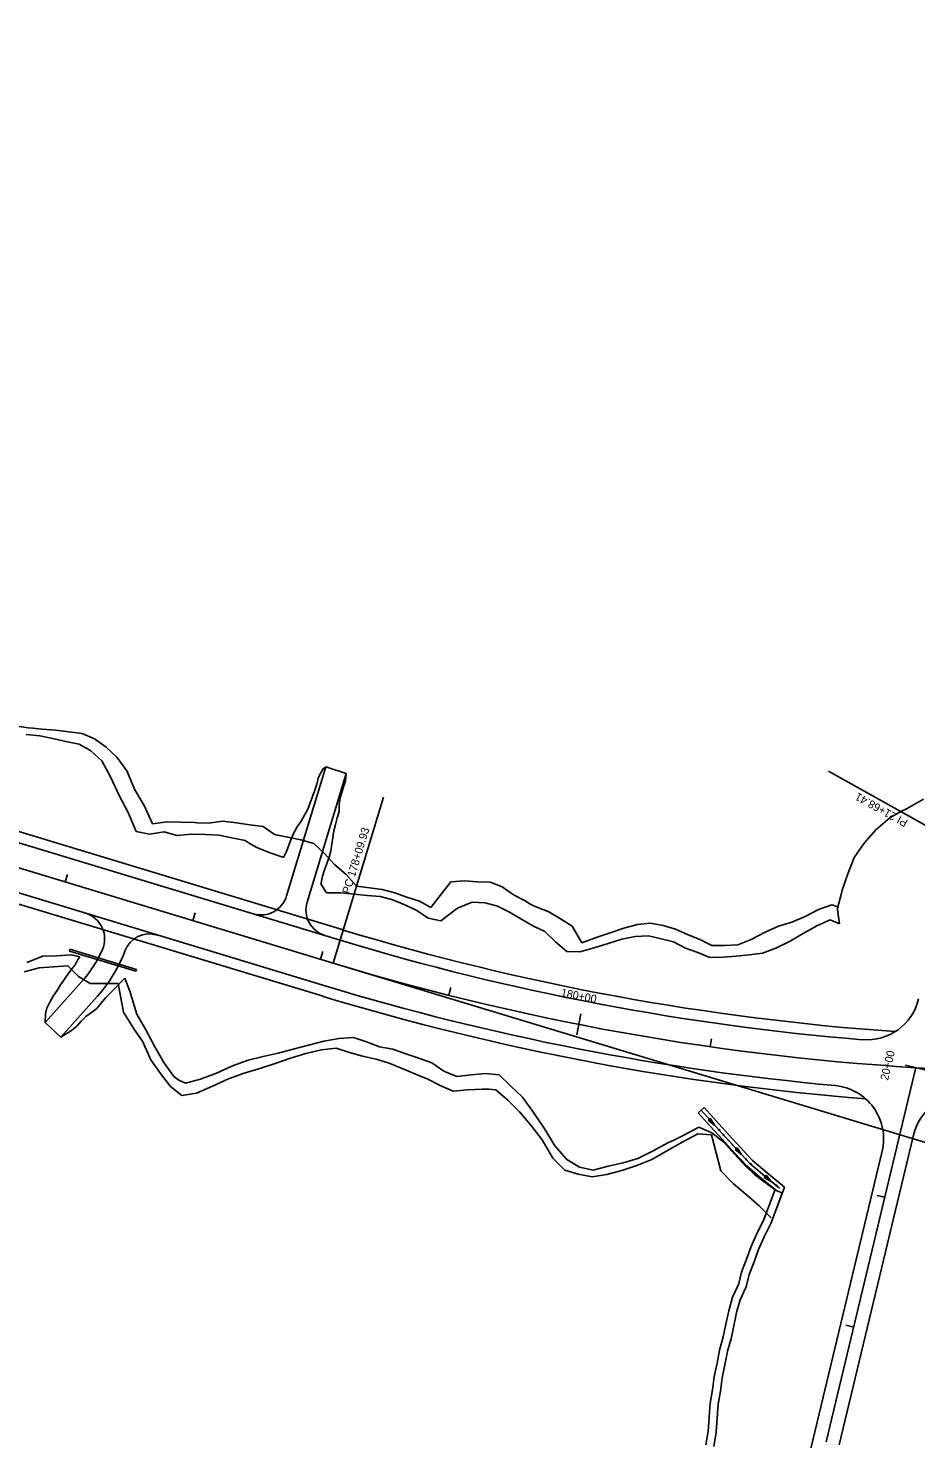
# Model space of a CAD drawing. Extents: x 979959 to 994833, y 1835619 to 1845316.
# Drawn here: x 983405 to 984070, y 1837450 to 1838507 of the extents above; entities that cross this region are included whole.
import ezdxf

# ---------------------------------------------------------------- set-up
doc = ezdxf.new("R2010")
doc.units = 0
for name, color, linetype in [('Future 5 Lane Construction Limits', 7, 'Continuous'), ('R_CONCRETE', 7, 'Continuous'), ('R_Drainage', 7, 'Continuous'), ('R_Horz Alg', 7, 'Continuous'), ('R_Horz Alg Annot', 7, 'Continuous'), ('R_Horz Alg Annot_Side Road', 7, 'Continuous'), ('R_Horz Alg Stationing', 7, 'Continuous'), ('R_Horz Alg Stationing_Side Road', 7, 'Continuous'), ('R_Proposed Const Limits', 7, 'Continuous'), ('R_Proposed Road', 7, 'Continuous'), ('R_Special Ditch', 7, 'Continuous')]:
    doc.layers.add(name, color=color, linetype=linetype)

msp = doc.modelspace()

# ---------------------------------------------------------------- linework, layer by layer
at = {"layer": 'Future 5 Lane Construction Limits'}
for points in [[(983394.6, 1837984.2), (983404.6, 1837982.7), (983408.1, 1837982.4), (983414.8, 1837981.8), (983425, 1837980.9), (983435.1, 1837979.8), (983445.1, 1837978.4), (983454.4, 1837974.4), (983463, 1837968.3), (983471.1, 1837960.8), (983478.5, 1837950.5), (983484.6, 1837936.2), (983491.5, 1837924.6), (983497.8, 1837910.8)], [(983497.8, 1837910.8), (983508.7, 1837912.4), (983519.1, 1837912.1), (983529.4, 1837911.7), (983531.3, 1837911.6), (983539.7, 1837911.3), (983550.6, 1837912.7), (983560.7, 1837911.5), (983570.7, 1837910.1), (983580.8, 1837908.7), (983589.4, 1837902.9), (983599.2, 1837900.7), (983609.1, 1837898.9), (983618.7, 1837896), (983626.9, 1837888.6), (983634.7, 1837880), (983643, 1837872.7), (983650.8, 1837864)], [(983650.8, 1837864), (983660.6, 1837862.9), (983670.2, 1837861.5), (983679.6, 1837859), (983688.7, 1837855.8), (983698, 1837852.9), (983706.7, 1837848.1)], [(983706.7, 1837848.1), (983721.7, 1837867.2), (983731.8, 1837868), (983741.4, 1837867.2), (983751.2, 1837867), (983760.2, 1837863.6), (983768.6, 1837857.5), (983777.3, 1837853), (983781.6, 1837850.3), (983786.1, 1837848.3), (983795.2, 1837844.9), (983803.8, 1837839.6), (983812.5, 1837834.2), (983819.8, 1837821.7)], [(983819.8, 1837821.7), (983830.5, 1837825.7), (983841, 1837829.1), (983851.4, 1837832.7), (983861.6, 1837835.3), (983871.5, 1837836.3), (983881, 1837834.6), (983890.2, 1837831.9), (983899.2, 1837827.8), (983908.3, 1837824.1), (983917.4, 1837819.6), (983927.1, 1837819.5), (983936.8, 1837820), (983947, 1837824.1), (983957.4, 1837829.6), (983967.5, 1837834), (983977.4, 1837837.1), (983987.4, 1837841.4), (983997.5, 1837846.6), (984007.3, 1837850), (984011.7, 1837848.7)], [(983401.6, 1837799.9), (983412.9, 1837802.8), (983423.6, 1837803.7), (983434.2, 1837804.3)], [(983434.2, 1837804.3), (983442.3, 1837796.3), (983451.1, 1837791), (983461.6, 1837791.2), (983472, 1837791.1)], [(983472, 1837791.1), (983476, 1837769.6), (983483, 1837758.3), (983484.4, 1837756.4), (983490.3, 1837747.9), (983496.5, 1837733.8), (983503.9, 1837723.6), (983511.4, 1837714), (983519.8, 1837707.2), (983530.8, 1837709), (983542.8, 1837714.1), (983554.9, 1837719.7), (983566.6, 1837723.8), (983578.2, 1837727.5), (983589.7, 1837731.1), (983601.4, 1837735.2), (983612.9, 1837738.7), (983624.5, 1837741.4), (983635.7, 1837742.7)], [(983635.7, 1837742.7), (983645.5, 1837739.5), (983655.4, 1837736.7), (983665.5, 1837734.3), (983675.4, 1837731.5), (983685, 1837727.4), (983694.6, 1837723.5), (983704.3, 1837719.5), (983713.7, 1837714.7), (983723.3, 1837710.4), (983734.2, 1837711.3), (983745, 1837712), (983750.2, 1837712), (983755.4, 1837711.5)], [(983755.4, 1837711.5), (983764.3, 1837703.6), (983773, 1837694.9), (983781.5, 1837684.9), (983790, 1837673.9), (983798, 1837660.3), (983807, 1837651.3), (983817.1, 1837648.3), (983827.5, 1837646.3), (983838.6, 1837648), (983849.8, 1837651), (983861.1, 1837654.6), (983872.4, 1837659.3), (983884.1, 1837666), (983895.6, 1837672.4), (983906.9, 1837678.4), (983917.2, 1837677.6)], [(983917.2, 1837677.6), (983924.1, 1837650.6), (983933.5, 1837641.2), (983943.1, 1837633), (983952.7, 1837624.8), (983961.9, 1837615.4)]]:
    msp.add_lwpolyline(points, dxfattribs=at)
at = {"layer": 'R_CONCRETE'}
msp.add_line((983907.2, 1837694.2), (983911.7, 1837698.2), dxfattribs=at)
for points in [[(983907.2, 1837694.2), (983916.2, 1837684.2), (983925.3, 1837674.1), (983934.4, 1837664.2), (983943.8, 1837654.2), (983953.5, 1837645.9), (983964.8, 1837636.6)], [(983911.7, 1837698.2), (983920.6, 1837688.2), (983929.7, 1837678.2), (983938.8, 1837668.3), (983948, 1837658.5), (983957.4, 1837650.5), (983971.9, 1837638.5)], [(983913, 1837445.2), (983914.6, 1837455.3), (983915.3, 1837466), (983916.2, 1837476.5), (983917.9, 1837486.5), (983919.1, 1837496.6), (983921.3, 1837506.6), (983923.2, 1837516.4), (983923.6, 1837518.1), (983926, 1837526.3), (983928, 1837535.8), (983930.1, 1837545.8), (983933, 1837556.1), (983937.4, 1837565.5), (983937.7, 1837566.3), (983939.7, 1837574.8), (983943.5, 1837584.5), (983946.9, 1837594.1), (983951.1, 1837603.7), (983955.8, 1837613), (983956.3, 1837614.1), (983964.8, 1837636.6)], [(983918.9, 1837444.1), (983920.6, 1837454.7), (983921.3, 1837465.5), (983922.2, 1837475.7), (983923.8, 1837485.6), (983925.1, 1837495.6), (983927.2, 1837505.4), (983929.1, 1837515.2), (983929.4, 1837516.6), (983931.8, 1837524.8), (983933.9, 1837534.6), (983935.9, 1837544.4), (983938.7, 1837554), (983943, 1837563.3), (983943.4, 1837564.7), (983945.4, 1837573), (983949.1, 1837582.4), (983952.5, 1837591.8), (983956.6, 1837601.2), (983961.1, 1837610.3), (983961.8, 1837611.7), (983971.9, 1837638.5)]]:
    msp.add_lwpolyline(points, dxfattribs=at)
at = {"layer": 'R_Drainage'}
for p, q in [((983435.9, 1837816.8), (983435.5, 1837815.3)), ((983485.3, 1837800.3), (983435.5, 1837815.3)), ((983485.7, 1837801.7), (983435.9, 1837816.8)), ((983485.7, 1837801.7), (983485.3, 1837800.3))]:
    msp.add_line(p, q, dxfattribs=at)
at = {"layer": 'R_Horz Alg'}
for p, q in [((981399.3, 1838482.3), (983633.3, 1837806.4)), ((984003.1, 1837447.5), (984070.4, 1837728.1))]:
    msp.add_line(p, q, dxfattribs=at)
msp.add_arc((984186.3, 1839634.4), 1909.9, 253.1679, 281.6644, dxfattribs=at)
at = {"layer": 'R_Horz Alg Annot'}
msp.add_lwpolyline([(983633.3, 1837806.4), (983671, 1837930.8)], dxfattribs=at)
at = {"layer": 'R_Horz Alg Annot_Side Road'}
msp.add_line((983633.3, 1837806.4), (984097.5, 1837666), dxfattribs=at)
msp.add_lwpolyline([(984109.7, 1837891.9), (984004.8, 1837950.2)], dxfattribs=at)
at = {"layer": 'R_Horz Alg Stationing'}
for points in [[(983434.1, 1837872.9), (983432.4, 1837867.2)], [(983529.8, 1837844), (983528.1, 1837838.2)], [(983625.5, 1837815), (983623.8, 1837809.3)], [(983721.6, 1837788.2), (983720.1, 1837782.4)], [(983819.2, 1837768.4), (983816.1, 1837752.7)], [(983917.1, 1837749.7), (983916.2, 1837743.8)]]:
    msp.add_lwpolyline(points, dxfattribs=at)
at = {"layer": 'R_Horz Alg Stationing_Side Road'}
for points in [[(984062.6, 1837730), (984078.2, 1837726.2)], [(984041.3, 1837632.3), (984047.1, 1837630.9)], [(984018, 1837535), (984023.8, 1837533.6)]]:
    msp.add_lwpolyline(points, dxfattribs=at)
at = {"layer": 'R_Proposed Const Limits'}
for p, q in [((983896.3, 1837677.5), (983907.6, 1837683.4)), ((983926.3, 1837672.2), (983934.3, 1837663.2)), ((983934.3, 1837663.2), (983943.4, 1837653.5))]:
    msp.add_line(p, q, dxfattribs=at)
for points in [[(983403.1, 1837977.8), (983413.2, 1837976.7), (983423.1, 1837974.7), (983432.9, 1837972.5), (983442.7, 1837970.4), (983448.1, 1837967.5), (983448.2, 1837967.5), (983451.6, 1837965.4), (983459.8, 1837958), (983466.5, 1837945.4), (983472.9, 1837932.1), (983479.5, 1837919.2), (983480.9, 1837916.4), (983485.6, 1837905.1)], [(983622.3, 1837945.7), (983625.5, 1837951.8), (983627.8, 1837953.6)], [(983624.1, 1837865.9), (983624.4, 1837866.3), (983624.4, 1837866.6), (983625.4, 1837871.5), (983626.8, 1837876.3), (983628.6, 1837881), (983630.3, 1837885.7), (983631.6, 1837890.5), (983632.4, 1837895.5), (983633, 1837900.5), (983633.8, 1837905.5), (983635, 1837910.4), (983636.4, 1837915.2), (983637.8, 1837920), (983637.8, 1837925.2), (983638.5, 1837930.2), (983640, 1837935), (983641.1, 1837938.6), (983642.7, 1837943), (983643.1, 1837948.5)], [(983596.1, 1837885.5), (983596.1, 1837885.6), (983598.4, 1837890.1), (983600, 1837894.8), (983601.9, 1837899.5), (983603.8, 1837904.1), (983606.4, 1837908.6), (983609.2, 1837912.9), (983611.8, 1837917.4), (983614.2, 1837921.9), (983616.1, 1837926.5), (983617.9, 1837931.2), (983619.6, 1837935.9), (983621.1, 1837940.5), (983622.3, 1837945.7)], [(984013.2, 1837835.9), (984011.7, 1837846.4), (984011.8, 1837848.6), (984014.3, 1837857.9), (984015.2, 1837861.1), (984019.5, 1837873.4), (984024.2, 1837885.5), (984031.6, 1837896.4), (984040.5, 1837906.4), (984050.9, 1837915.4), (984059.2, 1837920), (984063.8, 1837922.4), (984076.2, 1837929.3)], [(983485.6, 1837905.1), (983495.5, 1837903.1), (983506.5, 1837904.9), (983516.1, 1837902.1), (983526.8, 1837903), (983537.2, 1837902.9), (983547.5, 1837902.3), (983557.3, 1837900.2), (983567.2, 1837898.4), (983571.1, 1837895.7), (983576, 1837893.1), (983585.3, 1837889.2), (983594.8, 1837886), (983596.1, 1837885.5)], [(983624.1, 1837865.9), (983628.4, 1837859.1)], [(983628.4, 1837859.1), (983638.8, 1837859), (983649, 1837858), (983658.8, 1837857), (983668.7, 1837856.3), (983678.1, 1837853.7), (983687.2, 1837850.2), (983696, 1837845.8), (983704.5, 1837840)], [(983704.5, 1837840), (983714.1, 1837838), (983726.5, 1837847.5), (983737.6, 1837852), (983737.6, 1837852), (983747.4, 1837851.6), (983756.7, 1837849.1), (983765.5, 1837844.6), (983774.2, 1837839.5), (983783, 1837834.3), (983792, 1837830.2), (983800.2, 1837822.4), (983808.6, 1837815.1)], [(983808.6, 1837815.1), (983818.4, 1837814.8), (983829, 1837817.9), (983839.5, 1837821.2), (983849.9, 1837824.4), (983860, 1837826.4), (983869.9, 1837826.8), (983879.3, 1837824.7), (983888.6, 1837822.3), (983897.6, 1837817.6), (983906.9, 1837814.4), (983910, 1837813.1), (983916, 1837810.5), (983925.8, 1837810.9), (983935.7, 1837811.5), (983945.5, 1837812.7), (983955.4, 1837813.9), (983965.5, 1837817.7), (983975.7, 1837822.5), (983986, 1837828.5), (983996.2, 1837834.4), (984006.2, 1837838.9), (984013.2, 1837835.9)], [(983403.6, 1837806.8), (983415.6, 1837811.6), (983426.1, 1837811.9), (983436.7, 1837812.6), (983443.3, 1837811.1)], [(983443.3, 1837811.1), (983441.6, 1837808.7), (983439.8, 1837805.1), (983437.3, 1837802), (983434.6, 1837798.4), (983431.7, 1837794.3), (983428.8, 1837790.2), (983426.2, 1837785.8), (983423.4, 1837781.6), (983420.8, 1837777.2), (983418.5, 1837772.6), (983417.6, 1837768.5), (983417.2, 1837761.8)], [(983477.1, 1837795.2), (983474.9, 1837792.9), (983470.8, 1837788.7), (983466.7, 1837784.6), (983462.7, 1837780.5), (983459.3, 1837776.3), (983456.1, 1837772.4), (983452.1, 1837769.4), (983447.9, 1837766.4), (983444.4, 1837762.8), (983441, 1837759.2), (983437, 1837755.9), (983429, 1837751)], [(983477.1, 1837795.2), (983480.7, 1837785.3), (983486, 1837768.2), (983492.9, 1837756.4), (983499.5, 1837743.7), (983506.3, 1837731.8), (983513.7, 1837721.5), (983517.6, 1837718.7), (983522.6, 1837716.4), (983533.9, 1837719.5), (983545.7, 1837723.9), (983557.9, 1837729.5), (983569.6, 1837733.6), (983580.8, 1837736.3), (983592.1, 1837739), (983603.4, 1837741.9), (983614.8, 1837745), (983626.4, 1837747.8), (983637.8, 1837750), (983648.6, 1837750.6)], [(983648.6, 1837750.6), (983658.4, 1837747.4), (983668, 1837743.7), (983678.2, 1837741.9), (983687.9, 1837738.4), (983697.6, 1837735.2), (983707.3, 1837731.7), (983707.3, 1837731.7), (983716.3, 1837725.3), (983726, 1837721.4), (983736.9, 1837722.6), (983747.6, 1837723.6), (983757.9, 1837722.6)], [(983757.9, 1837722.6), (983766.6, 1837714.2), (983775.3, 1837705.8), (983783.5, 1837694.3), (983791.7, 1837682.6), (983799.7, 1837669.4), (983808.5, 1837659.1), (983818.1, 1837653.5), (983828.4, 1837651.2), (983839.7, 1837654.2), (983850.8, 1837656.8), (983861.9, 1837660), (983873.5, 1837665.8), (983885, 1837672), (983888.8, 1837673.8), (983896.3, 1837677.5)], [(983907.6, 1837683.4), (983917.5, 1837679.2), (983926.3, 1837672.2)], [(983955.5, 1837643.5), (983949.4, 1837647.9), (983943.3, 1837653.6)], [(983955.5, 1837643.5), (983964.8, 1837636.5), (983970.1, 1837633.9)], [(983918.9, 1837444.1), (983920.6, 1837454.7), (983921.3, 1837465.5), (983922.2, 1837475.7), (983923.8, 1837485.6), (983925.1, 1837495.6), (983927.2, 1837505.4), (983929.1, 1837515.2), (983929.4, 1837516.6), (983931.8, 1837524.8), (983933.9, 1837534.6), (983935.9, 1837544.4), (983938.7, 1837554), (983943, 1837563.3), (983943.4, 1837564.7), (983945.4, 1837573), (983949.1, 1837582.4), (983952.5, 1837591.8), (983956.6, 1837601.2), (983961.1, 1837610.3), (983961.8, 1837611.7), (983970.1, 1837633.9)]]:
    msp.add_lwpolyline(points, dxfattribs=at)
at = {"layer": 'R_Proposed Road'}
for p, q in [((981406.9, 1838507.1), (983640.8, 1837831.3)), ((981404.5, 1838499.5), (983638.5, 1837823.6)), ((981394.1, 1838465), (983628.1, 1837789.2)), ((981391.8, 1838457.4), (983625.8, 1837781.5)), ((983627.8, 1837953.6), (983598.4, 1837856.7)), ((983643, 1837948.6), (983613.7, 1837852)), ((983627.8, 1837953.6), (983643, 1837948.6)), ((983417.2, 1837761.8), (983444.6, 1837792.4)), ((983429, 1837751), (983456.5, 1837781.7)), ((983417.2, 1837761.8), (983429, 1837751)), ((984012.9, 1837445.2), (984068.6, 1837677.5)), ((983993.4, 1837449.9), (984045.1, 1837665.5))]:
    msp.add_line(p, q, dxfattribs=at)
for centre, radius, start, end in [((983579.3, 1837862.5), 20, 253.1679, 343.1679), ((983632.9, 1837846.2), 20, 163.1679, 253.1679), ((983441.9, 1837824.6), 20, 336.1594, 73.1679), ((984186.3, 1839634.4), 1883.9, 253.1679, 266.004), ((983495.7, 1837808.3), 20, 73.1679, 159.2323), ((984186.3, 1839634.4), 1891.9, 253.1679, 265.2678), ((983376.1, 1837853.7), 92, 318.1679, 336.1594), ((983376.1, 1837853.7), 108, 318.1679, 339.2323), ((984186.3, 1839634.4), 1927.9, 253.1679, 264.7484), ((984186.3, 1839634.4), 1935.9, 253.1679, 265.453), ((984033.6, 1837788.9), 40, 265.2678, 346.5199), ((984006.2, 1837674.8), 40, 346.5199, 84.7484), ((984107.5, 1837668.2), 40, 87.7026, 166.5199), ((985117.5, 1837180.4), 1155.9, 166.5199, 176.9167)]:
    msp.add_arc(centre, radius, start, end, dxfattribs=at)
at = {"layer": 'R_Special Ditch'}
for p, q in [((983916.2, 1837690.2), (983914.7, 1837688.8)), ((983914.7, 1837688.8), (983919.4, 1837685)), ((983919.4, 1837685), (983916.2, 1837690.2)), ((983936.4, 1837668), (983934.9, 1837666.6)), ((983934.9, 1837666.6), (983939.7, 1837662.9)), ((983939.7, 1837662.9), (983936.4, 1837668)), ((983958.1, 1837647.4), (983956.7, 1837645.8)), ((983956.7, 1837645.8), (983962, 1837642.8)), ((983962, 1837642.8), (983958.1, 1837647.4))]:
    msp.add_line(p, q, dxfattribs=at)
for points in [[(983909.5, 1837696.2), (983918.4, 1837686.2), (983927.5, 1837676.2), (983936.6, 1837666.2), (983945.9, 1837656.3), (983955.5, 1837648.2), (983968.1, 1837637.7)], [(983909.5, 1837696.2), (983918.4, 1837686.2), (983919.4, 1837685)], [(983929.5, 1837673.9), (983929.6, 1837673.9)], [(983929.6, 1837673.9), (983936.6, 1837666.2), (983939.7, 1837662.9)], [(983950.5, 1837652.5), (983950.5, 1837652.4)], [(983950.5, 1837652.4), (983955.5, 1837648.2), (983962, 1837642.8)]]:
    msp.add_lwpolyline(points, dxfattribs=at)
for centre in [(983922.8, 1837681.4), (983926.2, 1837677.6), (983943.2, 1837659.3), (983946.7, 1837655.7), (983965.9, 1837639.6)]:
    msp.add_circle(centre, 0.375, dxfattribs=at)

# ---------------------------------------------------------------- texts
at = {"layer": 'R_Horz Alg Annot'}
msp.add_text('PC 178+09.93', height=6, rotation=73.1679, dxfattribs=at).set_placement((983645.7, 1837857.7))
at = {"layer": 'R_Horz Alg Annot_Side Road'}
msp.add_text('PI 21+68.41', height=6, rotation=150.8956, dxfattribs=at).set_placement((984065, 1837913.3))
at = {"layer": 'R_Horz Alg Stationing'}
msp.add_text('180+00', height=6, rotation=348.8699, dxfattribs=at).set_placement((983803.8, 1837781.6))
at = {"layer": 'R_Horz Alg Stationing_Side Road'}
msp.add_text('20+00', height=6, rotation=76.5199, dxfattribs=at).set_placement((984049.5, 1837718.1))

doc.saveas('drawing.dxf')
